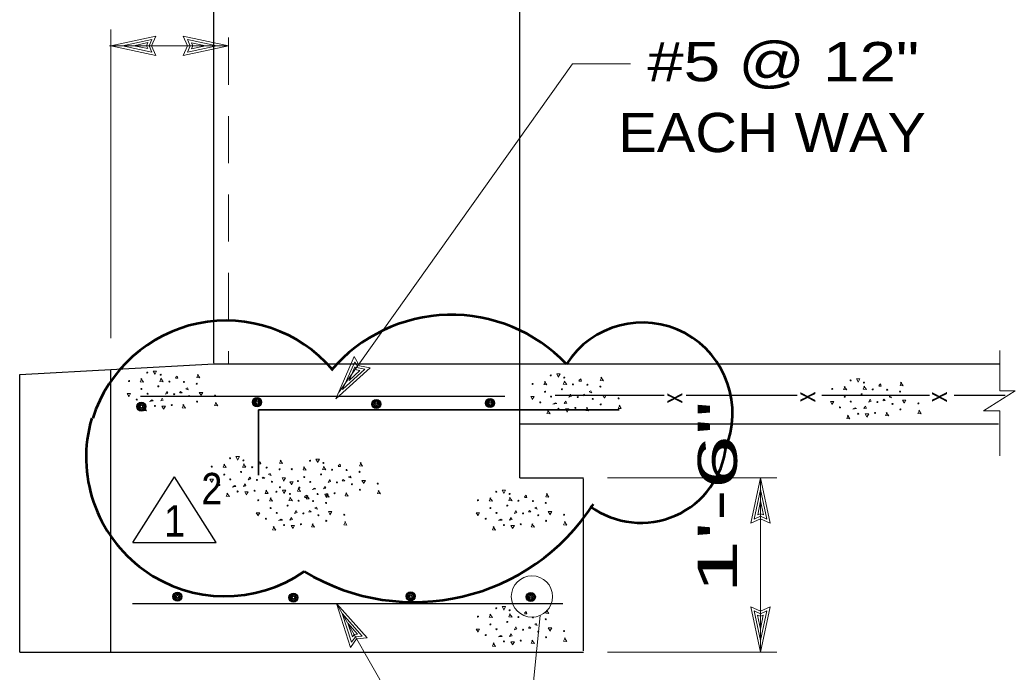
# Model space of a CAD drawing. Extents: x -28.1 to 13.9, y -16.1 to 13.9.
# Drawn here: x -16.347 to -13.173, y 2.425 to 4.504 of the extents above; entities that cross this region are included whole.
import ezdxf
from ezdxf.enums import TextEntityAlignment as Align

# ---------------------------------------------------------------- set-up
doc = ezdxf.new("R2010")
doc.units = 0
doc.header["$LTSCALE"] = 0.05
doc.linetypes.add('MEDIUM_DASHED', pattern=[4.5, 3, -1.5])
doc.layers.add('1', color=7, linetype='Continuous', lineweight=13)
doc.layers.add('2', color=7, linetype='Continuous', lineweight=13)

msp = doc.modelspace()

# ---------------------------------------------------------------- linework, layer by layer
at = {"layer": '1', "lineweight": 25}
for p, q in [((-14.75304, 3.04369), (-14.75304, 10.01569)), ((-15.72804, 3.40969), (-15.72804, 7.37069)), ((-16.34704, 2.48869), (-16.34704, 3.37369)), ((-16.05704, 2.48869), (-16.05704, 3.38969)), ((-15.96204, 3.30469), (-14.80004, 3.30469)), ((-14.64004, 3.30769), (-14.29204, 3.30769)), ((-14.22204, 3.30769), (-13.86804, 3.30769)), ((-13.78904, 3.30769), (-13.44604, 3.30769)), ((-13.36704, 3.30769), (-13.20504, 3.30769)), ((-14.75304, 3.21669), (-13.22604, 3.21669)), ((-15.9872, 2.83793), (-15.8542, 3.04693)), ((-15.7212, 2.83793), (-15.8542, 3.04693)), ((-14.75304, 3.04369), (-14.55004, 3.04369)), ((-14.55004, 2.49269), (-14.55004, 3.04069)), ((-15.9872, 2.83793), (-15.7212, 2.83793)), ((-15.98804, 2.64369), (-14.61504, 2.64369)), ((-16.34704, 2.48869), (-14.55004, 2.48869))]:
    msp.add_line(p, q, dxfattribs=at)
at = {"layer": '1', "linetype": 'MEDIUM_DASHED'}
msp.add_line((-15.68204, 7.44769), (-15.68204, 3.40769), dxfattribs=at)
at = {"layer": '1'}
for p, q in [((-16.05704, 3.48969), (-16.05704, 4.47369)), ((-16.05704, 4.42169), (-15.91304, 4.45269)), ((-15.68204, 4.42169), (-15.82604, 4.45269)), ((-16.06104, 4.42169), (-15.68204, 4.42169)), ((-16.05704, 4.42169), (-15.91304, 4.39069)), ((-16.02004, 4.42169), (-15.92604, 4.44169)), ((-16.02004, 4.42169), (-15.92604, 4.40169)), ((-15.98404, 4.42169), (-15.93904, 4.43169)), ((-15.98404, 4.42169), (-15.93904, 4.41269)), ((-15.93904, 4.43169), (-15.94304, 4.42169)), ((-15.94304, 4.42169), (-15.93904, 4.41269)), ((-15.92604, 4.44169), (-15.93504, 4.42169)), ((-15.93504, 4.42169), (-15.92604, 4.40169)), ((-15.68204, 4.42169), (-15.82604, 4.39069)), ((-15.71904, 4.42169), (-15.81304, 4.44169)), ((-15.80404, 4.42169), (-15.81304, 4.44169)), ((-15.71904, 4.42169), (-15.81304, 4.40169)), ((-15.81304, 4.40169), (-15.80404, 4.42169)), ((-15.75504, 4.42169), (-15.80004, 4.43069)), ((-15.79604, 4.42169), (-15.80004, 4.43069)), ((-15.75504, 4.42169), (-15.80004, 4.41169)), ((-15.80004, 4.41169), (-15.79604, 4.42169)), ((-15.33904, 3.29569), (-15.28104, 3.43069)), ((-13.22204, 3.32169), (-13.22204, 3.44969)), ((-15.31804, 3.32569), (-15.27904, 3.41369)), ((-15.29704, 3.35469), (-15.27904, 3.39769)), ((-15.27904, 3.41369), (-15.26804, 3.39469)), ((-15.27904, 3.39769), (-15.27304, 3.38869)), ((-15.33904, 3.29569), (-15.23004, 3.39469)), ((-15.31804, 3.32569), (-15.24704, 3.39069)), ((-15.29704, 3.35469), (-15.26304, 3.38669)), ((-15.27304, 3.38869), (-15.26304, 3.38669)), ((-15.26804, 3.39469), (-15.24704, 3.39069)), ((-13.27404, 3.25769), (-13.17304, 3.32169)), ((-13.22204, 3.32169), (-13.17304, 3.32169)), ((-13.27404, 3.25769), (-13.22204, 3.25769)), ((-13.22204, 3.11469), (-13.22204, 3.25769)), ((-14.47304, 3.04369), (-13.93304, 3.04369)), ((-13.98504, 3.04369), (-14.01604, 2.89969)), ((-13.98504, 2.48869), (-13.98504, 3.04369)), ((-13.98504, 3.04369), (-13.95404, 2.89969)), ((-13.98504, 3.00669), (-14.00504, 2.91269)), ((-13.98504, 3.00669), (-13.96504, 2.91269)), ((-13.98504, 2.97069), (-13.99404, 2.92569)), ((-13.98504, 2.97069), (-13.97504, 2.92569)), ((-13.98504, 2.92169), (-14.00504, 2.91269)), ((-13.98504, 2.92969), (-13.99404, 2.92569)), ((-13.97504, 2.92569), (-13.98504, 2.92969)), ((-13.96504, 2.91269), (-13.98504, 2.92169)), ((-15.33704, 2.64369), (-14.76104, 1.63369)), ((-15.33704, 2.64369), (-15.23904, 2.53369)), ((-15.33704, 2.64369), (-15.29304, 2.50369)), ((-15.31904, 2.61169), (-15.25504, 2.53969)), ((-15.31904, 2.61169), (-15.28904, 2.51969)), ((-13.98504, 2.48869), (-14.01604, 2.63269)), ((-13.98504, 2.52569), (-14.00504, 2.61969)), ((-14.00504, 2.61969), (-13.98504, 2.61069)), ((-13.98504, 2.56169), (-13.99504, 2.60669)), ((-13.99504, 2.60669), (-13.98504, 2.60269)), ((-13.98504, 2.48869), (-13.95404, 2.63269)), ((-13.98504, 2.52569), (-13.96504, 2.61969)), ((-13.98504, 2.61069), (-13.96504, 2.61969)), ((-13.98504, 2.56169), (-13.97604, 2.60669)), ((-13.98504, 2.60269), (-13.97604, 2.60669)), ((-15.30104, 2.58069), (-15.28604, 2.53669)), ((-15.30104, 2.58069), (-15.27004, 2.54569)), ((-15.28104, 2.54469), (-15.28604, 2.53669)), ((-15.27004, 2.54569), (-15.28104, 2.54469)), ((-15.25504, 2.53969), (-15.27704, 2.53769)), ((-15.27704, 2.53769), (-15.28904, 2.51969)), ((-14.47304, 2.48869), (-13.93304, 2.48869))]:
    msp.add_line(p, q, dxfattribs=at)
at = {"layer": '1', "lineweight": 35}
for q in [(-14.43545, 3.2612), (-15.58575, 3.05286)]:
    msp.add_line((-15.58575, 3.2612), q, dxfattribs=at)
at = {"layer": '1'}
for points in [[(-15.91304, 4.45269), (-15.92704, 4.42169), (-15.91304, 4.39069)], [(-15.82604, 4.39069), (-15.81204, 4.42169), (-15.82604, 4.45269)], [(-15.33104, 3.31569), (-14.58504, 4.36369), (-14.40004, 4.36369)], [(-15.28104, 3.43069), (-15.26404, 3.40169), (-15.23004, 3.39469)], [(-13.95404, 2.89969), (-13.98504, 2.91369), (-14.01604, 2.89969)], [(-14.68804, 2.60569), (-14.74304, 2.05769), (-14.56504, 2.05769)], [(-14.01604, 2.63269), (-13.98504, 2.61869), (-13.95404, 2.63269)], [(-15.23904, 2.53369), (-15.27304, 2.53069), (-15.29304, 2.50369)]]:
    msp.add_lwpolyline(points, dxfattribs=at)
at = {"layer": '1', "lineweight": 25}
msp.add_lwpolyline([(-16.34704, 3.37369), (-15.72904, 3.40769), (-13.22204, 3.40769)], dxfattribs=at)
for centre, radius in [((-15.95957, 3.27141), 0.01445), ((-15.95957, 3.27141), 0.01121), ((-15.95957, 3.27141), 0.00822), ((-15.95957, 3.27141), 0.00415), ((-15.59057, 3.28541), 0.01445), ((-15.59057, 3.28541), 0.01121), ((-15.59057, 3.28541), 0.00822), ((-15.59057, 3.28541), 0.00415), ((-15.21057, 3.27941), 0.01445), ((-15.21057, 3.27941), 0.01121), ((-15.21057, 3.27941), 0.00822), ((-15.21057, 3.27941), 0.00415), ((-14.84757, 3.28241), 0.01445), ((-14.84757, 3.28241), 0.01121), ((-14.84757, 3.28241), 0.00822), ((-14.84757, 3.28241), 0.00415), ((-15.84457, 2.66541), 0.01445), ((-15.84457, 2.66541), 0.01121), ((-15.84457, 2.66541), 0.00822), ((-15.84457, 2.66541), 0.00415), ((-15.47457, 2.66241), 0.01445), ((-15.47457, 2.66241), 0.01121), ((-15.47457, 2.66241), 0.00822), ((-15.47457, 2.66241), 0.00415), ((-15.10057, 2.66641), 0.01445), ((-15.10057, 2.66641), 0.01121), ((-15.10057, 2.66641), 0.00822), ((-15.10057, 2.66641), 0.00415), ((-14.71757, 2.66441), 0.01445), ((-14.71757, 2.66441), 0.01121), ((-14.71757, 2.66441), 0.00822), ((-14.71757, 2.66441), 0.00415)]:
    msp.add_circle(centre, radius, dxfattribs=at)
at = {"layer": '1'}
msp.add_circle((-14.71404, 2.66569), 0.0658, dxfattribs=at)
at = {"layer": '1', "lineweight": 53}
for centre, radius, start, end in [((-14.97026, 3.05858), 0.50528, 43.54651, 139.4817), ((-15.68939, 3.09895), 0.44639, 40.71845, 162.29106), ((-14.3618, 3.25127), 0.2878, 336.28955, 147.31561), ((-15.69262, 3.10982), 0.44328, 163.63164, 304.69306), ((-14.36642, 3.17358), 0.27289, 233.69374, 354.08588), ((-15.08994, 3.32797), 0.67987, 238.97877, 327.25989)]:
    msp.add_arc(centre, radius, start, end, dxfattribs=at)
at = {"layer": '2'}
for p, q in [((-15.85104, 3.36369), (-15.84504, 3.36869)), ((-14.56404, 3.35469), (-14.55804, 3.35969)), ((-13.60804, 3.33869), (-13.60204, 3.34369)), ((-15.58704, 3.09069), (-15.58104, 3.09569)), ((-15.33204, 3.08269), (-15.32604, 3.08769)), ((-15.43904, 2.98369), (-15.43304, 2.98869)), ((-14.73804, 2.98369), (-14.73204, 2.98869)), ((-14.73804, 2.61269), (-14.73204, 2.61769))]:
    msp.add_line(p, q, dxfattribs=at)
for points in [[(-15.91704, 3.37569), (-15.92204, 3.38469), (-15.91104, 3.38469), (-15.91704, 3.37369)], [(-15.84504, 3.36869), (-15.84304, 3.36169), (-15.85104, 3.36169)], [(-15.77804, 3.37369), (-15.78304, 3.36369), (-15.77304, 3.36269), (-15.78104, 3.37369)], [(-14.63004, 3.36669), (-14.63504, 3.37569), (-14.62404, 3.37569), (-14.63004, 3.36469)], [(-14.49104, 3.36469), (-14.49604, 3.35469), (-14.48604, 3.35369), (-14.49404, 3.36469)], [(-15.95804, 3.36069), (-15.96304, 3.35069), (-15.95304, 3.34969), (-15.96104, 3.36069)], [(-15.89604, 3.36169), (-15.90104, 3.35169), (-15.89004, 3.35069), (-15.89804, 3.36169)], [(-14.67104, 3.35169), (-14.67604, 3.34169), (-14.66604, 3.34069), (-14.67404, 3.35169)], [(-14.60904, 3.35269), (-14.61404, 3.34269), (-14.60304, 3.34169), (-14.61104, 3.35269)], [(-14.55804, 3.35969), (-14.55604, 3.35269), (-14.56404, 3.35269)], [(-13.71504, 3.33569), (-13.72004, 3.32569), (-13.71004, 3.32469), (-13.71804, 3.33569)], [(-13.67404, 3.35069), (-13.67904, 3.35969), (-13.66804, 3.35969), (-13.67404, 3.34869)], [(-13.65304, 3.33669), (-13.65804, 3.32669), (-13.64704, 3.32569), (-13.65504, 3.33669)], [(-13.60204, 3.34369), (-13.60004, 3.33669), (-13.60804, 3.33669)], [(-13.53504, 3.34869), (-13.54004, 3.33869), (-13.53004, 3.33769), (-13.53804, 3.34869)], [(-16.00004, 3.30469), (-16.00504, 3.31269), (-15.99404, 3.31269), (-16.00004, 3.30269)], [(-15.83804, 3.31569), (-15.83504, 3.31969), (-15.83004, 3.31569), (-15.83704, 3.31469)], [(-15.81804, 3.32869), (-15.81304, 3.33069), (-15.81004, 3.32469), (-15.81804, 3.32769)], [(-15.77004, 3.30869), (-15.77504, 3.31669), (-15.76404, 3.31669), (-15.77004, 3.30669)], [(-14.71304, 3.29569), (-14.71804, 3.30369), (-14.70704, 3.30369), (-14.71304, 3.29369)], [(-14.55104, 3.30669), (-14.54804, 3.31069), (-14.54304, 3.30669), (-14.55004, 3.30569)], [(-14.53104, 3.31969), (-14.52604, 3.32169), (-14.52304, 3.31569), (-14.53104, 3.31869)], [(-14.48304, 3.29969), (-14.48804, 3.30769), (-14.47704, 3.30769), (-14.48304, 3.29769)], [(-13.57504, 3.30369), (-13.57004, 3.30569), (-13.56704, 3.29969), (-13.57504, 3.30269)], [(-15.93104, 3.28969), (-15.92604, 3.29269), (-15.92204, 3.28969), (-15.93404, 3.28769)], [(-15.88904, 3.26369), (-15.89404, 3.27269), (-15.88304, 3.27269), (-15.88904, 3.26269)], [(-15.82404, 3.27769), (-15.82904, 3.26769), (-15.81904, 3.26669), (-15.82704, 3.27769)], [(-15.72104, 3.28469), (-15.72604, 3.27469), (-15.71604, 3.27369), (-15.72304, 3.28469)], [(-14.64404, 3.28069), (-14.63904, 3.28369), (-14.63504, 3.28069), (-14.64704, 3.27869)], [(-14.43404, 3.27569), (-14.43904, 3.26569), (-14.42904, 3.26469), (-14.43604, 3.27569)], [(-13.75704, 3.27969), (-13.76204, 3.28769), (-13.75104, 3.28769), (-13.75704, 3.27769)], [(-13.59504, 3.29069), (-13.59204, 3.29469), (-13.58704, 3.29069), (-13.59404, 3.28969)], [(-13.52704, 3.28369), (-13.53204, 3.29169), (-13.52104, 3.29169), (-13.52704, 3.28169)], [(-15.94804, 3.26869), (-15.95304, 3.25869), (-15.94304, 3.25769), (-15.95104, 3.26869)], [(-14.66104, 3.25969), (-14.66604, 3.24969), (-14.65604, 3.24869), (-14.66404, 3.25969)], [(-14.60204, 3.25469), (-14.60704, 3.26369), (-14.59604, 3.26369), (-14.60204, 3.25369)], [(-14.53704, 3.26869), (-14.54204, 3.25869), (-14.53204, 3.25769), (-14.54004, 3.26869)], [(-13.70504, 3.24369), (-13.71004, 3.23369), (-13.70004, 3.23269), (-13.70804, 3.24369)], [(-13.68804, 3.26469), (-13.68304, 3.26769), (-13.67904, 3.26469), (-13.69104, 3.26269)], [(-13.64604, 3.23869), (-13.65104, 3.24769), (-13.64004, 3.24769), (-13.64604, 3.23769)], [(-13.58104, 3.25269), (-13.58604, 3.24269), (-13.57604, 3.24169), (-13.58404, 3.25269)], [(-13.47804, 3.25969), (-13.48304, 3.24969), (-13.47304, 3.24869), (-13.48004, 3.25969)], [(-15.65304, 3.10269), (-15.65804, 3.11169), (-15.64704, 3.11169), (-15.65304, 3.10069)], [(-15.69404, 3.08769), (-15.69904, 3.07769), (-15.68904, 3.07669), (-15.69704, 3.08769)], [(-15.63204, 3.08869), (-15.63704, 3.07869), (-15.62604, 3.07769), (-15.63404, 3.08869)], [(-15.58104, 3.09569), (-15.57904, 3.08869), (-15.58704, 3.08869)], [(-15.51404, 3.10069), (-15.51904, 3.09069), (-15.50904, 3.08969), (-15.51704, 3.10069)], [(-15.43904, 3.07969), (-15.44404, 3.06969), (-15.43404, 3.06869), (-15.44204, 3.07969)], [(-15.39804, 3.09469), (-15.40304, 3.10369), (-15.39204, 3.10369), (-15.39804, 3.09269)], [(-15.37704, 3.08069), (-15.38204, 3.07069), (-15.37104, 3.06969), (-15.37904, 3.08069)], [(-15.32604, 3.08769), (-15.32404, 3.08069), (-15.33204, 3.08069)], [(-15.25904, 3.09269), (-15.26404, 3.08269), (-15.25404, 3.08169), (-15.26204, 3.09269)], [(-15.55404, 3.05569), (-15.54904, 3.05769), (-15.54604, 3.05169), (-15.55404, 3.05469)], [(-15.29904, 3.04769), (-15.29404, 3.04969), (-15.29104, 3.04369), (-15.29904, 3.04669)], [(-15.73604, 3.03169), (-15.74104, 3.03969), (-15.73004, 3.03969), (-15.73604, 3.02969)], [(-15.66704, 3.01669), (-15.66204, 3.01969), (-15.65804, 3.01669), (-15.67004, 3.01469)], [(-15.57404, 3.04269), (-15.57104, 3.04669), (-15.56604, 3.04269), (-15.57304, 3.04169)], [(-15.50604, 3.03569), (-15.51104, 3.04369), (-15.50004, 3.04369), (-15.50604, 3.03369)], [(-15.48104, 3.02369), (-15.48604, 3.03169), (-15.47504, 3.03169), (-15.48104, 3.02169)], [(-15.31904, 3.03469), (-15.31604, 3.03869), (-15.31104, 3.03469), (-15.31804, 3.03369)], [(-15.25104, 3.02769), (-15.25604, 3.03569), (-15.24504, 3.03569), (-15.25104, 3.02569)], [(-15.68404, 2.99569), (-15.68904, 2.98569), (-15.67904, 2.98469), (-15.68704, 2.99569)], [(-15.62504, 2.99069), (-15.63004, 2.99969), (-15.61904, 2.99969), (-15.62504, 2.98969)], [(-15.56004, 3.00469), (-15.56504, 2.99469), (-15.55504, 2.99369), (-15.56304, 3.00469)], [(-15.50504, 2.99569), (-15.51004, 3.00469), (-15.49904, 3.00469), (-15.50504, 2.99369)], [(-15.45704, 3.01169), (-15.46204, 3.00169), (-15.45204, 3.00069), (-15.45904, 3.01169)], [(-15.43304, 2.98869), (-15.43104, 2.98169), (-15.43904, 2.98169)], [(-15.42904, 2.98769), (-15.43404, 2.97769), (-15.42404, 2.97669), (-15.43204, 2.98769)], [(-15.41204, 3.00869), (-15.40704, 3.01169), (-15.40304, 3.00869), (-15.41504, 3.00669)], [(-15.37004, 2.98269), (-15.37504, 2.99169), (-15.36404, 2.99169), (-15.37004, 2.98169)], [(-15.36604, 2.99369), (-15.37104, 2.98369), (-15.36104, 2.98269), (-15.36904, 2.99369)], [(-15.30504, 2.99669), (-15.31004, 2.98669), (-15.30004, 2.98569), (-15.30804, 2.99669)], [(-15.20204, 3.00369), (-15.20704, 2.99369), (-15.19704, 2.99269), (-15.20404, 3.00369)], [(-14.80404, 2.99569), (-14.80904, 3.00469), (-14.79804, 3.00469), (-14.80404, 2.99369)], [(-14.73204, 2.98869), (-14.73004, 2.98169), (-14.73804, 2.98169)], [(-14.66504, 2.99369), (-14.67004, 2.98369), (-14.66004, 2.98269), (-14.66804, 2.99369)], [(-15.54604, 2.98069), (-15.55104, 2.97069), (-15.54104, 2.96969), (-15.54904, 2.98069)], [(-15.48404, 2.98169), (-15.48904, 2.97169), (-15.47804, 2.97069), (-15.48604, 2.98169)], [(-14.84504, 2.98069), (-14.85004, 2.97069), (-14.84004, 2.96969), (-14.84804, 2.98069)], [(-14.78304, 2.98169), (-14.78804, 2.97169), (-14.77704, 2.97069), (-14.78504, 2.98169)], [(-15.58804, 2.92469), (-15.59304, 2.93269), (-15.58204, 2.93269), (-15.58804, 2.92269)], [(-15.42604, 2.93569), (-15.42304, 2.93969), (-15.41804, 2.93569), (-15.42504, 2.93469)], [(-15.40604, 2.94869), (-15.40104, 2.95069), (-15.39804, 2.94469), (-15.40604, 2.94769)], [(-15.35804, 2.92869), (-15.36304, 2.93669), (-15.35204, 2.93669), (-15.35804, 2.92669)], [(-14.88704, 2.92469), (-14.89204, 2.93269), (-14.88104, 2.93269), (-14.88704, 2.92269)], [(-14.72504, 2.93569), (-14.72204, 2.93969), (-14.71704, 2.93569), (-14.72404, 2.93469)], [(-14.70504, 2.94869), (-14.70004, 2.95069), (-14.69704, 2.94469), (-14.70504, 2.94769)], [(-14.65704, 2.92869), (-14.66204, 2.93669), (-14.65104, 2.93669), (-14.65704, 2.92669)], [(-15.53604, 2.88869), (-15.54104, 2.87869), (-15.53104, 2.87769), (-15.53904, 2.88869)], [(-15.51904, 2.90969), (-15.51404, 2.91269), (-15.51004, 2.90969), (-15.52204, 2.90769)], [(-15.47704, 2.88369), (-15.48204, 2.89269), (-15.47104, 2.89269), (-15.47704, 2.88269)], [(-15.41204, 2.89769), (-15.41704, 2.88769), (-15.40704, 2.88669), (-15.41504, 2.89769)], [(-15.30904, 2.90469), (-15.31404, 2.89469), (-15.30404, 2.89369), (-15.31104, 2.90469)], [(-14.83504, 2.88869), (-14.84004, 2.87869), (-14.83004, 2.87769), (-14.83804, 2.88869)], [(-14.81804, 2.90969), (-14.81304, 2.91269), (-14.80904, 2.90969), (-14.82104, 2.90769)], [(-14.77604, 2.88369), (-14.78104, 2.89269), (-14.77004, 2.89269), (-14.77604, 2.88269)], [(-14.71104, 2.89769), (-14.71604, 2.88769), (-14.70604, 2.88669), (-14.71404, 2.89769)], [(-14.60804, 2.90469), (-14.61304, 2.89469), (-14.60304, 2.89369), (-14.61004, 2.90469)], [(-14.84504, 2.60969), (-14.85004, 2.59969), (-14.84004, 2.59869), (-14.84804, 2.60969)], [(-14.80404, 2.62469), (-14.80904, 2.63369), (-14.79804, 2.63369), (-14.80404, 2.62269)], [(-14.78304, 2.61069), (-14.78804, 2.60069), (-14.77704, 2.59969), (-14.78504, 2.61069)], [(-14.73204, 2.61769), (-14.73004, 2.61069), (-14.73804, 2.61069)], [(-14.66504, 2.62269), (-14.67004, 2.61269), (-14.66004, 2.61169), (-14.66804, 2.62269)], [(-14.70504, 2.57769), (-14.70004, 2.57969), (-14.69704, 2.57369), (-14.70504, 2.57669)], [(-14.88704, 2.55369), (-14.89204, 2.56169), (-14.88104, 2.56169), (-14.88704, 2.55169)], [(-14.81804, 2.53869), (-14.81304, 2.54169), (-14.80904, 2.53869), (-14.82104, 2.53669)], [(-14.72504, 2.56469), (-14.72204, 2.56869), (-14.71704, 2.56469), (-14.72404, 2.56369)], [(-14.65704, 2.55769), (-14.66204, 2.56569), (-14.65104, 2.56569), (-14.65704, 2.55569)], [(-14.83504, 2.51769), (-14.84004, 2.50769), (-14.83004, 2.50669), (-14.83804, 2.51769)], [(-14.77604, 2.51269), (-14.78104, 2.52169), (-14.77004, 2.52169), (-14.77604, 2.51169)], [(-14.71104, 2.52669), (-14.71604, 2.51669), (-14.70604, 2.51569), (-14.71404, 2.52669)], [(-14.60804, 2.53369), (-14.61304, 2.52369), (-14.60304, 2.52269), (-14.61004, 2.53369)]]:
    msp.add_lwpolyline(points, dxfattribs=at)
for points in [[(-15.88304, 3.31069), (-15.87804, 3.31969), (-15.87504, 3.31369)], [(-14.59604, 3.30169), (-14.59104, 3.31069), (-14.58804, 3.30469)], [(-15.89804, 3.28969), (-15.89304, 3.29769), (-15.89004, 3.29169)], [(-14.61104, 3.28069), (-14.60604, 3.28869), (-14.60304, 3.28269)], [(-13.65504, 3.26469), (-13.65004, 3.27269), (-13.64704, 3.26669)], [(-13.64004, 3.28569), (-13.63504, 3.29469), (-13.63204, 3.28869)], [(-15.63404, 3.01669), (-15.62904, 3.02469), (-15.62604, 3.01869)], [(-15.61904, 3.03769), (-15.61404, 3.04669), (-15.61104, 3.04069)], [(-15.37904, 3.00869), (-15.37404, 3.01669), (-15.37104, 3.01069)], [(-15.36404, 3.02969), (-15.35904, 3.03869), (-15.35604, 3.03269)], [(-15.47104, 2.93069), (-15.46604, 2.93969), (-15.46304, 2.93369)], [(-14.77004, 2.93069), (-14.76504, 2.93969), (-14.76204, 2.93369)], [(-15.48604, 2.90969), (-15.48104, 2.91769), (-15.47804, 2.91169)], [(-14.78504, 2.90969), (-14.78004, 2.91769), (-14.77704, 2.91169)], [(-14.78504, 2.53869), (-14.78004, 2.54669), (-14.77704, 2.54069)], [(-14.77004, 2.55969), (-14.76504, 2.56869), (-14.76204, 2.56269)]]:
    msp.add_lwpolyline(points, close=True, dxfattribs=at)
for centre in [(-15.94079, 3.37956), (-15.89804, 3.37281), (-14.65379, 3.37056), (-14.61104, 3.36381), (-15.99904, 3.35281), (-15.90554, 3.33581), (-15.87029, 3.35106), (-15.82404, 3.35006), (-15.78279, 3.34431), (-14.71204, 3.34381), (-14.58329, 3.34206), (-14.53704, 3.34106), (-14.49579, 3.33531), (-13.69779, 3.35456), (-13.65504, 3.34781), (-15.95929, 3.32756), (-15.94004, 3.31231), (-15.85504, 3.31056), (-15.80704, 3.30481), (-15.72454, 3.30656), (-14.67229, 3.31856), (-14.65304, 3.30331), (-14.61854, 3.32681), (-14.56804, 3.30156), (-13.75604, 3.32781), (-13.71629, 3.30256), (-13.66254, 3.31081), (-13.62729, 3.32606), (-13.58104, 3.32506), (-13.53979, 3.31931), (-15.97454, 3.29381), (-15.91654, 3.27356), (-15.86254, 3.27606), (-15.78179, 3.28706), (-14.68754, 3.28481), (-14.52004, 3.29581), (-14.49479, 3.27806), (-14.43754, 3.29756), (-13.73154, 3.26881), (-13.69704, 3.28731), (-13.61204, 3.28556), (-13.56404, 3.27981), (-13.48154, 3.28156), (-14.62954, 3.26456), (-14.57554, 3.26706), (-13.67354, 3.24856), (-13.61954, 3.25106), (-13.53879, 3.26206), (-15.73504, 3.07981), (-15.67679, 3.10656), (-15.63404, 3.09981), (-15.60629, 3.07806), (-15.42179, 3.09856), (-15.37904, 3.09181), (-15.69529, 3.05456), (-15.64154, 3.06281), (-15.56004, 3.07706), (-15.51879, 3.07131), (-15.48004, 3.07181), (-15.44029, 3.04656), (-15.38654, 3.05481), (-15.35129, 3.07006), (-15.30504, 3.06906), (-15.26379, 3.06331), (-15.71054, 3.02081), (-15.67604, 3.03931), (-15.59104, 3.03756), (-15.54304, 3.03181), (-15.51779, 3.01406), (-15.46054, 3.03356), (-15.42104, 3.03131), (-15.33604, 3.02956), (-15.28804, 3.02381), (-15.20554, 3.02556), (-15.65254, 3.00056), (-15.59854, 3.00306), (-15.52879, 2.99956), (-15.48604, 2.99281), (-15.45554, 3.01281), (-15.39754, 2.99256), (-15.34354, 2.99506), (-15.26279, 3.00606), (-14.82779, 2.99956), (-14.78504, 2.99281), (-15.58704, 2.97281), (-15.49354, 2.95581), (-15.45829, 2.97106), (-15.41204, 2.97006), (-15.37079, 2.96431), (-14.88604, 2.97281), (-14.79254, 2.95581), (-14.75729, 2.97106), (-14.71104, 2.97006), (-14.66979, 2.96431), (-15.54729, 2.94756), (-15.52804, 2.93231), (-15.44304, 2.93056), (-15.39504, 2.92481), (-15.31254, 2.92656), (-14.84629, 2.94756), (-14.82704, 2.93231), (-14.74204, 2.93056), (-14.69404, 2.92481), (-14.61154, 2.92656), (-15.56254, 2.91381), (-15.50454, 2.89356), (-15.45054, 2.89606), (-15.36979, 2.90706), (-14.86154, 2.91381), (-14.80354, 2.89356), (-14.74954, 2.89606), (-14.66879, 2.90706), (-14.88604, 2.60181), (-14.82779, 2.62856), (-14.78504, 2.62181), (-14.84629, 2.57656), (-14.79254, 2.58481), (-14.75729, 2.60006), (-14.71104, 2.59906), (-14.66979, 2.59331), (-14.86154, 2.54281), (-14.82704, 2.56131), (-14.74204, 2.55956), (-14.69404, 2.55381), (-14.61154, 2.55556), (-14.80354, 2.52256), (-14.74954, 2.52506), (-14.66879, 2.53606)]:
    msp.add_circle(centre, 0.00162, dxfattribs=at)

# ---------------------------------------------------------------- texts
at = {"layer": '1', "width": 1.25}
msp.add_text('#5 @ 12"', height=0.125, dxfattribs=at).set_placement((-14.34604, 4.30869))
at = {"layer": '1'}
for s, height, width, p in [('EACH WAY', 0.125, 1.1, (-13.94803, 4.08269)), ('2', 0.1, 0.9, (-15.73486, 2.95993)), ('1', 0.1, 0.9, (-15.85386, 2.85693))]:
    msp.add_text(s, height=height, dxfattribs=dict(at, width=width)).set_placement(p, align=Align.CENTER)
for s, height, width, p in [('x', 0.063, 0.8, (-14.23404, 3.29811)), ('x', 0.063, 0.8, (-13.81004, 3.30211)), ('x', 0.063, 0.8, (-13.39004, 3.30211)), ('1\'-6"', 0.125, 1.85, (-14.06004, 2.98232))]:
    msp.add_text(s, height=height, rotation=90, dxfattribs=dict(at, width=width)).set_placement(p, align=Align.CENTER)

doc.saveas('drawing.dxf')
